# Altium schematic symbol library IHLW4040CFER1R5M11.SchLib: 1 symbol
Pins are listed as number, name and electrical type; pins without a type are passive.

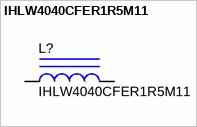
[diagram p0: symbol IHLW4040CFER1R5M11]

## IHLW4040CFER1R5M11
designator L?
Inductor, Shielded, Powdered Iron, 1.5 µH, 14.5 A, 0.0044 ohm, SMD, Winged Terminal; Manufacturer: Vishay-Dale; Value: 1.5uH; Ind_H: 1.5E-6; ValueDisplayed: 1.5µH; Imax_A: 15; Irms: 20A @ 40C rise; Isat: 14.5A @ 20% inductance drop; DCR_ohm: 0.0044; Value2: 14.5A
signal-integrity model Inductor
simulation model Inductor
footprint IHLW-4040CF (Footprint not found)
pins: 1, 2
